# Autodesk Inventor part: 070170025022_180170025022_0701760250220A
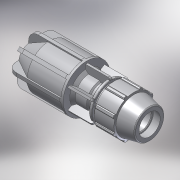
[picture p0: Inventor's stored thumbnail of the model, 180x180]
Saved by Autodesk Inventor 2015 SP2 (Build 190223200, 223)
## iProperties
Created: 2017-02
Part Number: 070170025022_180170025022_0701760250220A
Material: PVC-Piping
Description: PLASSON PLASS4 COUPLING 15-22*25
Document SubType Name: Modeling
Designer: KIM
Mass: 92.6774 g
Surface Area: 199.44 cm^2
Volume: 66.1981 cm^3
Density: 1.4 g/cm^3
Appearance: Smooth - White
Author: KIM
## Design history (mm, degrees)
derived "070170.ipt"
feature "Solid1::070170.ipt"
tag "TaggingFeature1"
body "Solid1"
other parameters: "d2" = 25, "d4" = 11.78571, "d5" = 20.3, "d7" = 54, "d8" = 31.55097, "d9" = 11.57143, "d11" = 4.125, "d12" = 43.2, "d13" = 120 deg, "d14" = 37.5, "d15" = 12 deg, "d16" = 48.6, "d18" = 1.25, "d19" = 35 deg, "d20" = 17.5 deg, "d21" = 50.22, "d23" = 0, "d25" = 360 deg, "d27" = 1.08, "d42" = 26.1, "d43" = 1.62, "d46" = 0.75, "d53" = 0.5, "d67" = 2.7, "d70" = 22.5, "d71" = 58, "d74" = 180 deg, "d75" = 22, "d76" = 64, "d80" = 22.5, "d84" = 60.8, "d85" = 135 deg, "d86" = 3.2, "d89" = 3.2, "d90" = 135 deg, "d94" = 3.2, "d97" = 4.32, "d98" = 0, "d100" = 360 deg, "d102" = 70.4, "d103" = 12.8, "d104" = 5.12, "d105" = 0, "d112" = 99, "d113" = 27.2, "d114" = 66, "d115" = 38.4, "d116" = 99, "d117" = 4, "d118" = 27, "d119" = 2.7, "d120" = 0, "d121" = 2.7, "d123" = 360 deg, "d_" = 25, "E_" = 54, "A_" = 81, "l_" = 58, "d_1" = 22, "E_1" = 64, "H_" = 165, "d106" = 31.55097
